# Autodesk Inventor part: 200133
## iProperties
Created: 2007-12
Part Number: 200133
Document SubType Name: Modeling
Designer: TH
Density: 7.85 g/cm^3
Mass: 53.4442 g
Surface Area: 55.5133 cm^2
Volume: 6.80817 cm^3
Material: Steel
Description: MOUNTING BRACKET
Component Category: Lower Component
Author: TH
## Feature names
1. Extrusion1
2. Extrusion2
3. Fillet1
4. Fillet2
5. Fillet3
6. Fillet4
7. Extrusion3
8. Extrusion4
9. Fillet5
10. Fillet6
11. Extrusion5
12. Hole1
13. Fillet7
